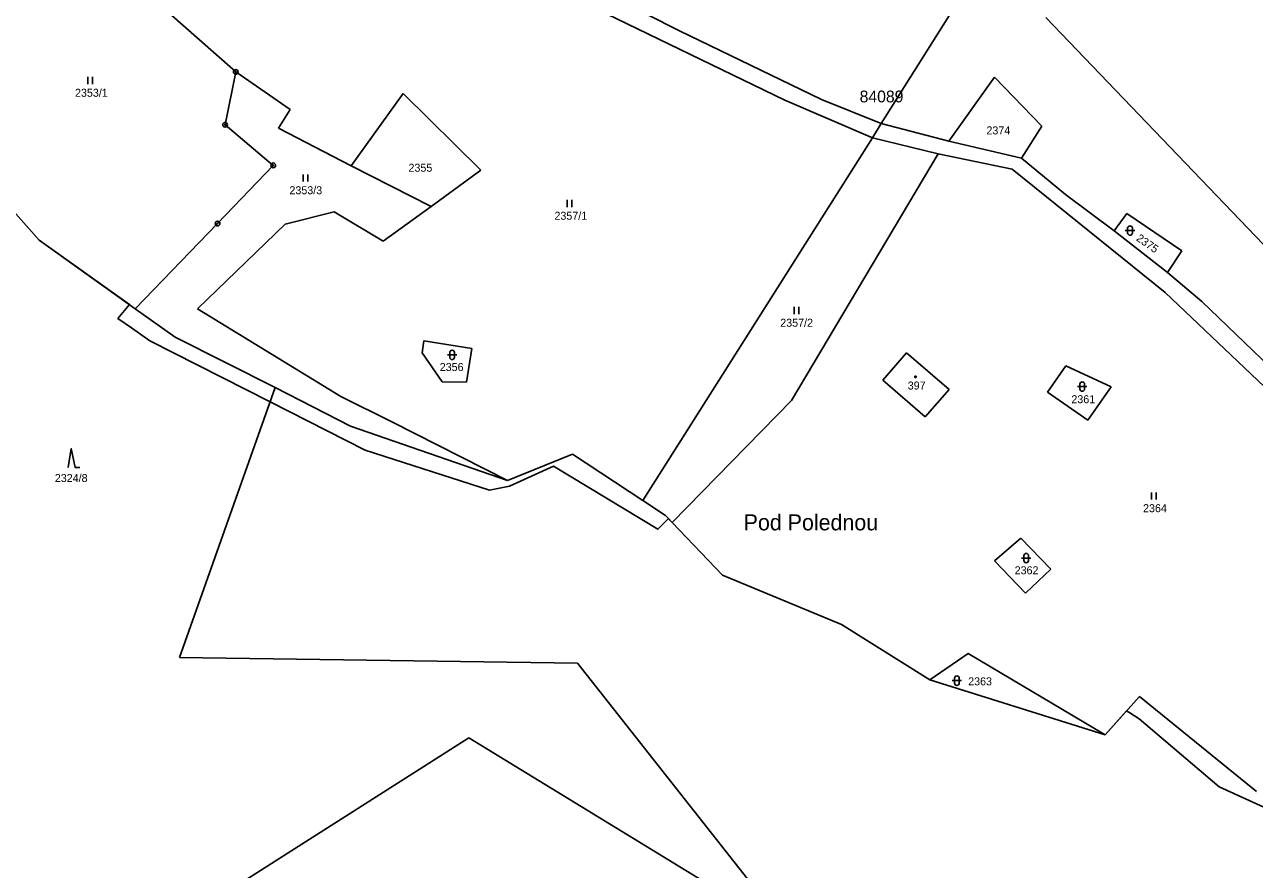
# Model space of a CAD drawing. Extents: x -439246 to -433691, y -1130252 to -1121148.
# Drawn here: x -437275.7 to -437014.4, y -1126201.8 to -1126022.3 of the extents above; entities that cross this region are included whole.
import ezdxf

# ---------------------------------------------------------------- set-up
doc = ezdxf.new("R2010")
doc.units = 0
for name, color, linetype in [('Vrstva 1', 7, 'Continuous'), ('Vrstva 18', 7, 'Continuous'), ('Vrstva 19', 7, 'Continuous'), ('Vrstva 24', 7, 'Continuous'), ('Vrstva 25', 7, 'Continuous'), ('Vrstva 3', 7, 'Continuous'), ('Vrstva 37', 7, 'Continuous'), ('Vrstva 52', 7, 'Continuous'), ('Vrstva 53', 7, 'Continuous'), ('Vrstva 6', 7, 'Continuous'), ('Vrstva 62', 7, 'Continuous')]:
    doc.layers.add(name, color=color, linetype=linetype)

msp = doc.modelspace()

# ---------------------------------------------------------------- linework, layer by layer
at = {"layer": 'Vrstva 1'}
for points in [[(-437093.65, -1126043.33), (-437072.6, -1126009.85)], [(-437252.1, -1126013.49), (-437230.81, -1126032.35)], [(-437157.39, -1126013.02), (-437136.53, -1126023.6)], [(-437114.11, -1126038.32), (-437156.55, -1126017.82)], [(-437058.65, -1126020.76), (-437009.2, -1126072.43)], [(-437136.53, -1126023.6), (-437106.34, -1126038.24)], [(-437230.81, -1126032.35), (-437233.07, -1126043.58)], [(-437219.23, -1126040.35), (-437230.81, -1126032.35)], [(-437079.26, -1126047.08), (-437069.56, -1126033.49)], [(-437069.56, -1126033.49), (-437059.5, -1126043.86)], [(-437195.23, -1126036.97), (-437206.3, -1126052.27)], [(-437178.71, -1126053.2), (-437195.23, -1126036.97)], [(-437095.54, -1126046.35), (-437114.11, -1126038.32)], [(-437106.34, -1126038.24), (-437093.65, -1126043.33)], [(-437221.71, -1126044.32), (-437219.23, -1126040.35)], [(-437233.07, -1126043.58), (-437222.84, -1126052.2)], [(-437206.3, -1126052.27), (-437221.71, -1126044.32)], [(-437093.65, -1126043.33), (-437095.54, -1126046.35)], [(-437093.65, -1126043.33), (-437079.26, -1126047.08)], [(-437059.5, -1126043.86), (-437063.86, -1126050.67)], [(-437095.54, -1126046.35), (-437144.29, -1126123.42)], [(-437081.57, -1126049.75), (-437095.54, -1126046.35)], [(-437063.86, -1126050.67), (-437079.26, -1126047.08)], [(-437112.72, -1126102.15), (-437081.57, -1126049.75)], [(-437081.57, -1126049.75), (-437065.83, -1126052.99)], [(-437063.86, -1126050.67), (-437054.53, -1126058.37)], [(-437222.84, -1126052.2), (-437234.67, -1126064.57)], [(-437206.3, -1126052.27), (-437189.31, -1126060.91)], [(-437189.31, -1126060.91), (-437178.71, -1126053.2)], [(-437065.83, -1126052.99), (-437033.31, -1126079.22)], [(-437054.53, -1126058.37), (-437044.19, -1126066.08)], [(-437279.71, -1126060.02), (-437272.57, -1126068.13)], [(-437199.51, -1126068.34), (-437189.31, -1126060.91)], [(-437220.33, -1126064.69), (-437209.88, -1126062.1)], [(-437209.88, -1126062.1), (-437199.51, -1126068.34)], [(-437041.46, -1126062.42), (-437044.19, -1126066.08)], [(-437029.77, -1126070.34), (-437041.46, -1126062.42)], [(-437234.67, -1126064.57), (-437252.16, -1126082.68)], [(-437238.94, -1126082.72), (-437220.33, -1126064.69)], [(-437044.19, -1126066.08), (-437032.82, -1126074.97)], [(-437272.57, -1126068.13), (-437252.16, -1126082.68)], [(-437032.82, -1126074.97), (-437029.77, -1126070.34)], [(-437032.82, -1126074.97), (-437025.54, -1126081.13)], [(-437033.31, -1126079.22), (-436981.36, -1126128.56)], [(-437025.54, -1126081.13), (-437001.92, -1126103.76)], [(-437252.16, -1126082.68), (-437243.68, -1126088.72)], [(-437208.5, -1126101.31), (-437238.94, -1126082.72)], [(-437243.68, -1126088.72), (-437222.4, -1126099.38)], [(-437191.21, -1126092), (-437190.82, -1126089.5)], [(-437190.82, -1126089.5), (-437180.63, -1126091.1)], [(-437186.97, -1126098.17), (-437191.21, -1126092)], [(-437180.63, -1126091.1), (-437181.76, -1126098.26)], [(-437093.29, -1126097.84), (-437088.25, -1126092.01)], [(-437088.25, -1126092.01), (-437079.25, -1126099.79)], [(-437054.43, -1126094.78), (-437058.32, -1126100.36)], [(-437044.81, -1126099.26), (-437054.43, -1126094.78)], [(-437222.4, -1126099.38), (-437206.46, -1126107.6)], [(-437181.76, -1126098.26), (-437186.97, -1126098.17)], [(-437093.29, -1126097.84), (-437084.29, -1126105.62)], [(-437084.29, -1126105.62), (-437079.25, -1126099.79)], [(-437058.32, -1126100.36), (-437049.77, -1126106.35)], [(-437049.77, -1126106.35), (-437044.81, -1126099.26)], [(-437197.62, -1126106.69), (-437208.5, -1126101.31)], [(-437138.07, -1126128.05), (-437112.72, -1126102.15)], [(-437206.46, -1126107.6), (-437173.09, -1126119.19)], [(-437197.62, -1126106.69), (-437173.09, -1126119.19)], [(-437173.09, -1126119.19), (-437159.27, -1126113.59)], [(-437159.27, -1126113.59), (-437144.29, -1126123.42)], [(-437144.29, -1126123.42), (-437139.46, -1126126.59)], [(-437138.07, -1126128.05), (-437139.46, -1126126.59)], [(-437138.07, -1126128.05), (-437127.38, -1126139.25)], [(-437063.97, -1126131.39), (-437069.61, -1126136.24)], [(-437057.63, -1126137.96), (-437063.97, -1126131.39)], [(-437069.61, -1126136.24), (-437062.98, -1126143.12)], [(-437127.38, -1126139.25), (-437102.09, -1126149.73)], [(-437062.98, -1126143.12), (-437057.63, -1126137.96)], [(-437102.09, -1126149.73), (-437083.36, -1126161.48)], [(-437075.18, -1126155.88), (-437083.36, -1126161.48)], [(-437046.08, -1126173.18), (-437075.18, -1126155.88)], [(-437083.36, -1126161.48), (-437046.08, -1126173.18)], [(-437046.08, -1126173.18), (-437038.78, -1126165.05)], [(-437038.78, -1126165.05), (-437013.92, -1126185.22)]]:
    msp.add_lwpolyline(points, dxfattribs=at)
at = {"layer": 'Vrstva 24'}
for centre, radius in [((-437230.81, -1126032.35), 0.5), ((-437230.81, -1126032.35), 0.1), ((-437233.07, -1126043.58), 0.5), ((-437233.07, -1126043.58), 0.1), ((-437222.84, -1126052.2), 0.5), ((-437222.84, -1126052.2), 0.1), ((-437234.67, -1126064.57), 0.5), ((-437234.67, -1126064.57), 0.1)]:
    msp.add_circle(centre, radius, dxfattribs=at)
at = {"layer": 'Vrstva 25'}
for p, q in [((-437262.26, -1126034.93), (-437262.26, -1126033.43)), ((-437261.26, -1126034.93), (-437261.26, -1126033.43)), ((-437216.47, -1126055.64), (-437216.47, -1126054.14)), ((-437215.47, -1126055.64), (-437215.47, -1126054.14)), ((-437160.37, -1126061.06), (-437160.37, -1126059.56)), ((-437159.37, -1126061.06), (-437159.37, -1126059.56)), ((-437041.79, -1126066.05), (-437039.79, -1126066.05)), ((-437041.29, -1126066.55), (-437041.29, -1126065.55)), ((-437040.29, -1126065.55), (-437040.29, -1126066.55)), ((-437112.16, -1126083.79), (-437112.16, -1126082.29)), ((-437111.16, -1126083.79), (-437111.16, -1126082.29)), ((-437185.84, -1126092.47), (-437183.84, -1126092.47)), ((-437185.34, -1126092.97), (-437185.34, -1126091.97)), ((-437184.34, -1126091.97), (-437184.34, -1126092.97)), ((-437051.94, -1126099.2), (-437049.94, -1126099.2)), ((-437051.44, -1126099.7), (-437051.44, -1126098.7)), ((-437050.44, -1126098.7), (-437050.44, -1126099.7)), ((-437036.26, -1126123.19), (-437036.26, -1126121.69)), ((-437035.26, -1126123.19), (-437035.26, -1126121.69)), ((-437063.84, -1126135.63), (-437061.84, -1126135.63)), ((-437063.34, -1126136.13), (-437063.34, -1126135.13)), ((-437062.34, -1126135.13), (-437062.34, -1126136.13)), ((-437078.58, -1126161.68), (-437076.58, -1126161.68)), ((-437078.08, -1126162.18), (-437078.08, -1126161.18)), ((-437077.08, -1126161.18), (-437077.08, -1126162.18))]:
    msp.add_line(p, q, dxfattribs=at)
msp.add_lwpolyline([(-437266.45, -1126116.36), (-437265.75, -1126112.36), (-437264.95, -1126116.36), (-437263.95, -1126116.36)], dxfattribs=at)
msp.add_circle((-437086.37, -1126097.13), 0.175, dxfattribs=at)
for centre, start, end in [((-437040.79, -1126065.55), 0, 180), ((-437040.79, -1126066.55), 180, 0), ((-437184.84, -1126091.97), 0, 180), ((-437184.84, -1126092.97), 180, 0), ((-437050.94, -1126098.7), 0, 180), ((-437050.94, -1126099.7), 180, 0), ((-437062.84, -1126135.13), 0, 180), ((-437062.84, -1126136.13), 180, 0), ((-437077.58, -1126161.18), 0, 180), ((-437077.58, -1126162.18), 180, 0)]:
    msp.add_arc(centre, 0.5, start, end, dxfattribs=at)
at = {"layer": 'Vrstva 3'}
for points in [[(-437093.29, -1126097.84), (-437088.25, -1126092.01)], [(-437088.25, -1126092.01), (-437079.25, -1126099.79)], [(-437093.29, -1126097.84), (-437084.29, -1126105.62)], [(-437084.29, -1126105.62), (-437079.25, -1126099.79)]]:
    msp.add_lwpolyline(points, dxfattribs=at)
at = {"layer": 'Vrstva 37'}
msp.add_circle((-437086.37, -1126097.13), 0.175, dxfattribs=at)
at = {"layer": 'Vrstva 52'}
msp.add_lwpolyline([(-437279.71, -1126060.02), (-437272.57, -1126068.13), (-437253.4, -1126081.79), (-437255.88, -1126084.73), (-437252.93, -1126086.7), (-437249.09, -1126089.47), (-437223.49, -1126102.45), (-437203.3, -1126112.68), (-437176.89, -1126121.2), (-437172.64, -1126120.35), (-437163.26, -1126116.09), (-437141.11, -1126129.51), (-437138.87, -1126127.21), (-437138.07, -1126128.05), (-437127.38, -1126139.25), (-437102.09, -1126149.73), (-437083.36, -1126161.48), (-437075.18, -1126155.88), (-437046.08, -1126173.18), (-437041.53, -1126168.11), (-437040.86, -1126168.53), (-437038.88, -1126169.76), (-437021.84, -1126184.25), (-436984.36, -1126201.28)], dxfattribs=at)
at = {"layer": 'Vrstva 6'}
for points in [[(-437242.76, -1126156.75), (-437222.4, -1126099.38)], [(-437158.2, -1126157.97), (-437242.76, -1126156.75)], [(-437112.59, -1126215.83), (-437158.2, -1126157.97)], [(-437181.3, -1126173.84), (-437276.03, -1126234.15)], [(-437181.3, -1126173.84), (-437112.59, -1126215.83)]]:
    msp.add_lwpolyline(points, dxfattribs=at)

# ---------------------------------------------------------------- texts
at = {"layer": 'Vrstva 18'}
for s, p in [('2353/1', (-437264.96, -1126037.63)), ('2374', (-437071.3, -1126045.63)), ('2355', (-437194.1, -1126053.56)), ('2353/3', (-437219.4, -1126058.34)), ('2357/1', (-437163.09, -1126063.76)), ('2357/2', (-437115.11, -1126086.49)), ('2356', (-437187.46, -1126095.9)), ('2361', (-437053.25, -1126102.74)), ('2324/8', (-437269.25, -1126119.48)), ('2364', (-437038.02, -1126125.89)), ('2362', (-437065.3, -1126139.08)), ('2363', (-437075.18, -1126162.68))]:
    msp.add_text(s, height=1.7, dxfattribs=at).set_placement(p)
msp.add_text('2375', height=1.7, rotation=324.7984, dxfattribs=at).set_placement((-437039.62, -1126068.03))
at = {"layer": 'Vrstva 19'}
msp.add_text('397', height=1.7, dxfattribs=at).set_placement((-437088.02, -1126099.83))
at = {"layer": 'Vrstva 53'}
msp.add_text('84089', height=2.5, dxfattribs=at).set_placement((-437098.24, -1126038.82))
at = {"layer": 'Vrstva 62'}
msp.add_text('Pod Polednou', height=3.4, dxfattribs=at).set_placement((-437122.88, -1126129.75))

doc.saveas('drawing.dxf')
